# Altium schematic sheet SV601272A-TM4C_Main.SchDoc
size 431 x 279 mm; Date: Not shown in title block; ApprovedBy: Not shown in title block; CheckedBy: Not shown in title block; Author: Not shown in title block; CompanyName: Not shown in title block; Engineer: Not shown in title block; Organization: Not shown in title block; Address1: Not shown in title block; Address2: Not shown in title block; Address3: Not shown in title block; Address4: Not shown in title block; DocumentNumber: 10; Revision: Use project parameter SCH_Rev; SheetNumber: 10; SheetTotal: 11; PageSetup: Record=PageOptions¦CenterHorizontal=True¦CenterVertical=True¦PrintScale=1.00¦XCorrection=1.00¦YCorrection=1.00¦PrintKind=0¦BorderSize=5000000¦LeftOffset=0¦BottomOffset=0¦Orientation=2¦PaperLength=1000¦PaperWidth=1000¦Scale=100¦PaperSource=15¦PrintQuality=600¦MediaType=1¦DitherType=10¦PaperKind=Letter¦PrintScaleMode=1
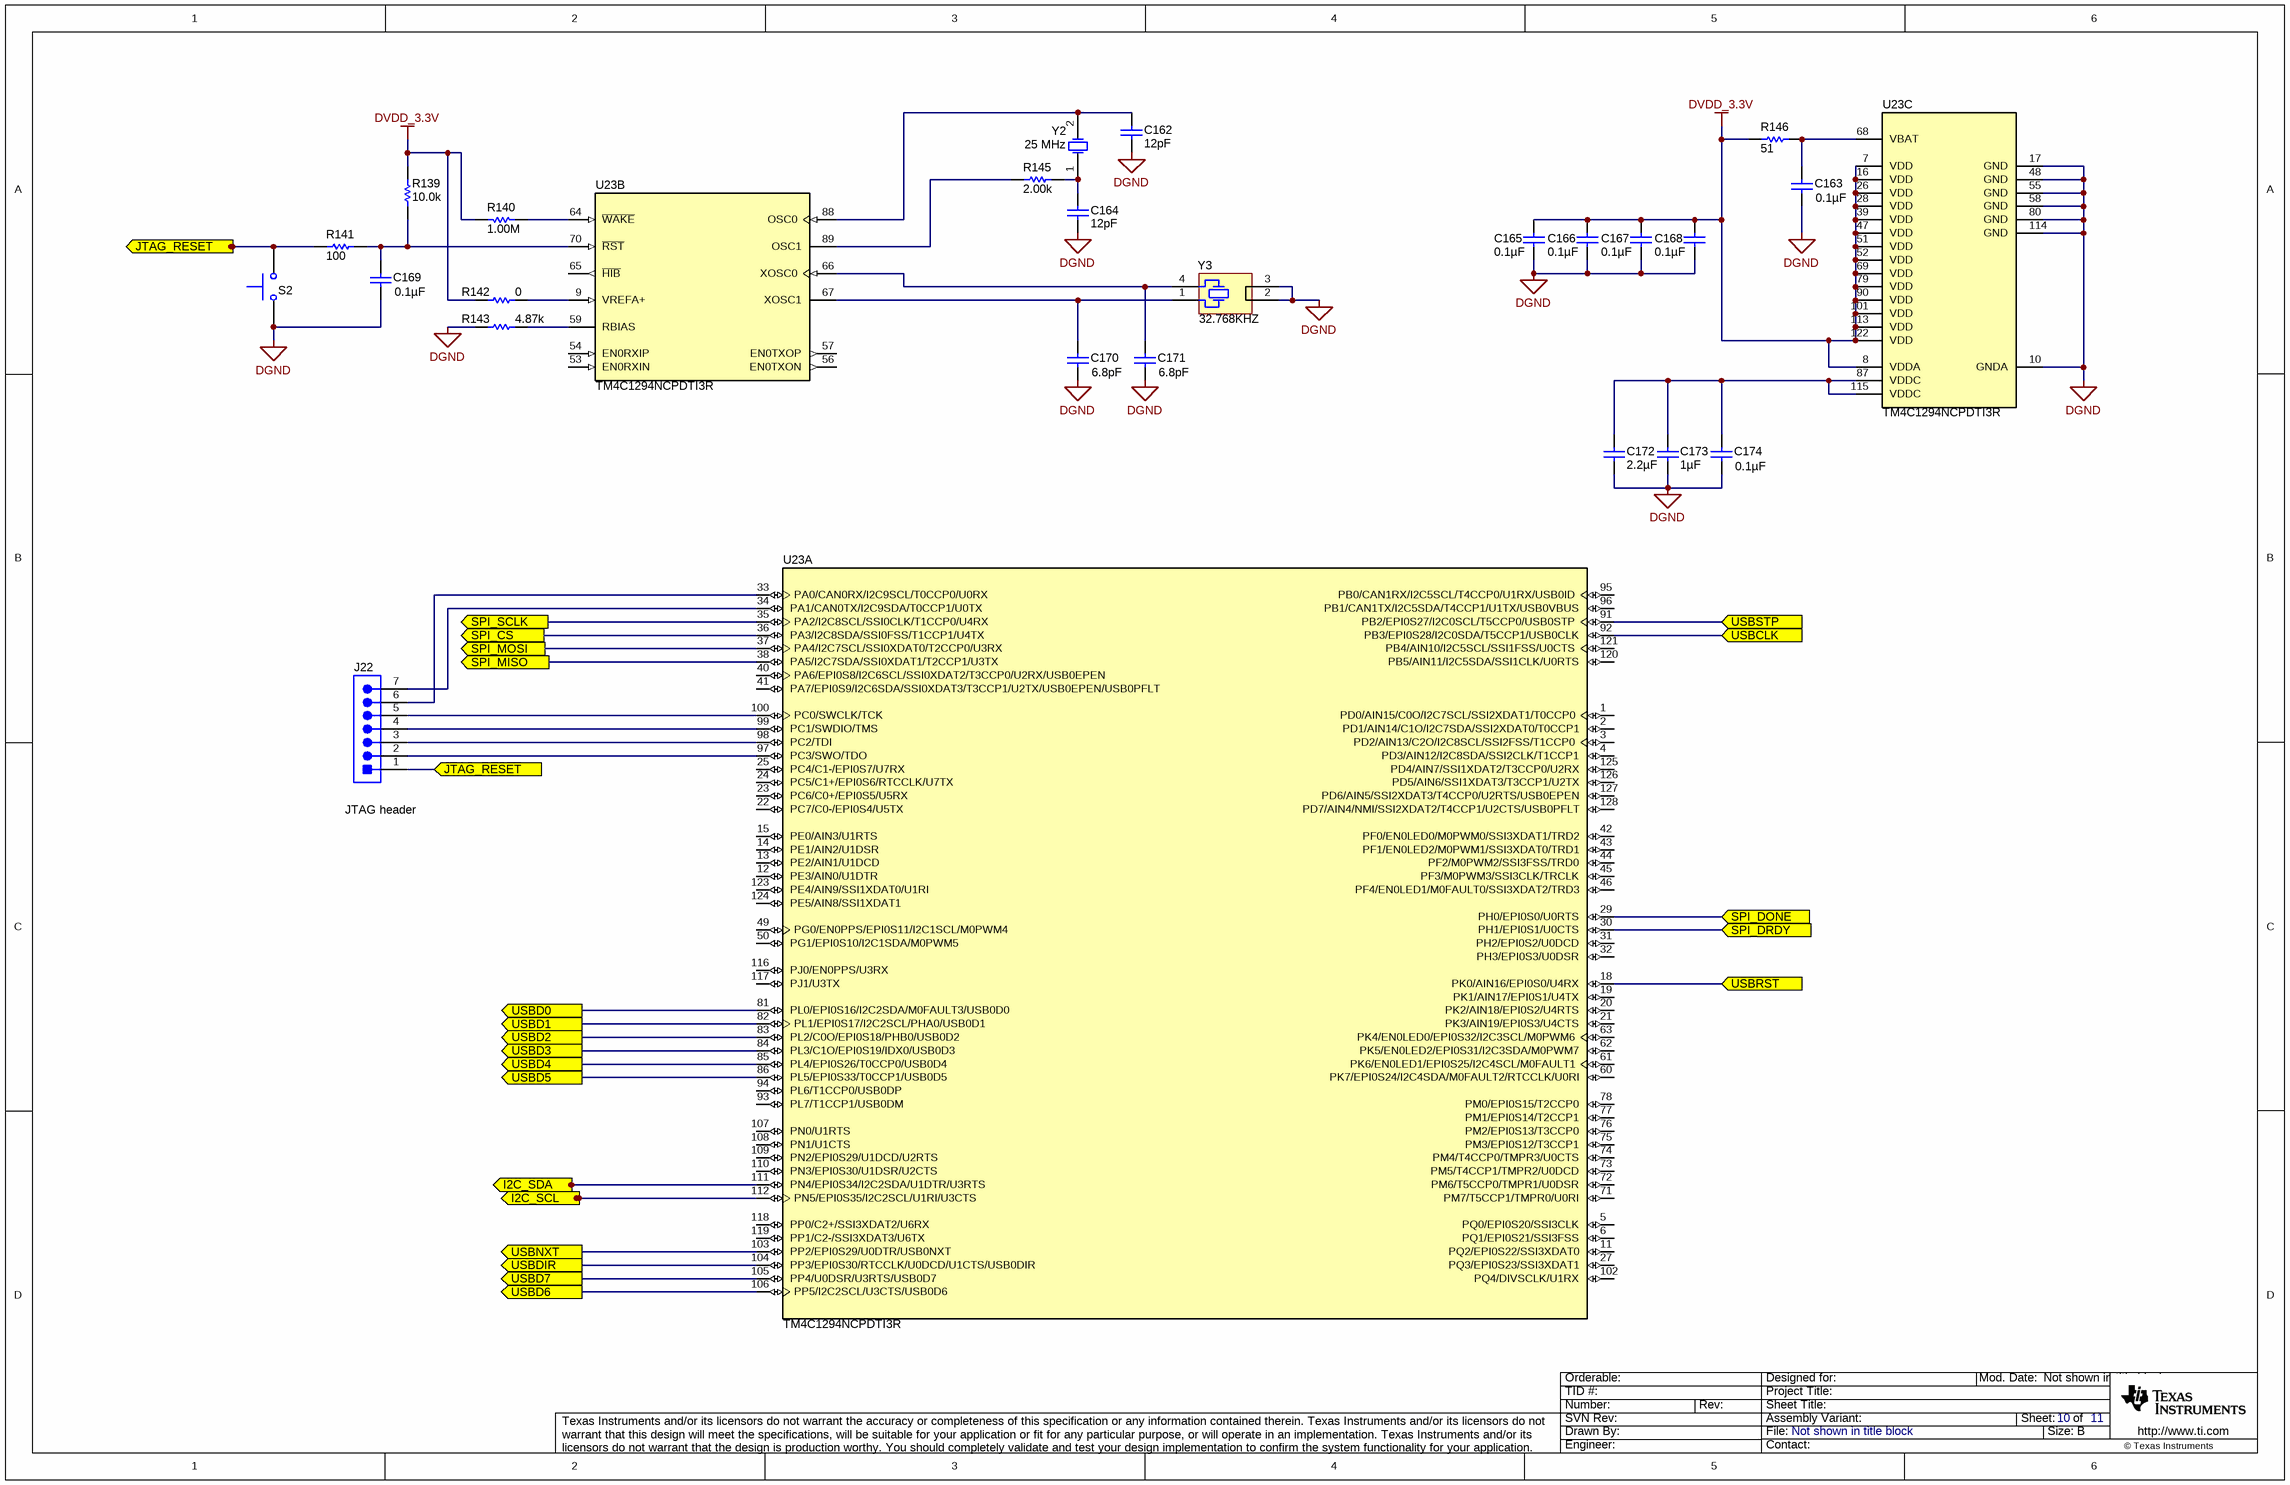
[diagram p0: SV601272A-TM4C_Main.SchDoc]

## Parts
C162  ValueDisplayed: 12pF  [0603]  (hidden comment: C0603C120J5GACTU)
C163  ValueDisplayed: 0.1µF  [0603]  (hidden comment: 06033C104JAT2A)
C164  ValueDisplayed: 12pF  [0603]  (hidden comment: C0603C120J5GACTU)
C165  ValueDisplayed: 0.1µF  [0603]  (hidden comment: 06033C104JAT2A)
C166  ValueDisplayed: 0.1µF  [0603]  (hidden comment: 06033C104JAT2A)
C167  ValueDisplayed: 0.1µF  [0603]  (hidden comment: 06033C104JAT2A)
C168  ValueDisplayed: 0.1µF  [0603]  (hidden comment: 06033C104JAT2A)
C169  ValueDisplayed: 0.1µF  [0603]  (hidden comment: 06033C104JAT2A)
C170  ValueDisplayed: 6.8pF  [0603]  (hidden comment: 06035A6R8CAT2A)
C171  ValueDisplayed: 6.8pF  [0603]  (hidden comment: 06035A6R8CAT2A)
C172  ValueDisplayed: 2.2µF  [0603]  (hidden comment: GRM188R6YA225KA12D)
C173  ValueDisplayed: 1µF  [0603]  (hidden comment: GRM188R71E105KA12D)
C174  ValueDisplayed: 0.1µF  [0603]  (hidden comment: 06033C104JAT2A)
J22  TSW-107-07-G-S  [TSW-107-07-G-S]  (value not drawn)
R139  ValueDisplayed: 10.0k  [0603]  (hidden comment: CRCW060310K0FKEA)
R140  ValueDisplayed: 1.00M  [0603]  (hidden comment: CRCW06031M00FKEA)
R141  ValueDisplayed: 100  [0603]  (hidden comment: CRCW0603100RFKEA)
R142  ValueDisplayed: 0  [0603]  (hidden comment: CRCW06030000Z0EA)
R143  ValueDisplayed: 4.87k  [0603]  (hidden comment: CRCW06034K87FKEA)
R145  ValueDisplayed: 2.00k  [0603]  (hidden comment: CRCW06032K00FKEA)
R146  ValueDisplayed: 51  [0603]  (hidden comment: CRCW060351R0JNEA)
S2  TL1015AF160QG  [SW_TL1015AF160QG]  (value not drawn)
U23  TM4C1294NCPDTI3R  [PDT0128A]  (parts A,B,C of 3)
Y2  Frequency: 25 MHz  [XTAL_ABM3]  (hidden comment: ABM3-25.000MHZ-D2Y-T)
Y3  Frequency: 32.768KHZ  [Seiko_SSP-T]  (hidden comment: SSPT7F-7PF20-R)

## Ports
I2C_SCL, I2C_SDA, JTAG_RESET, SPI_CS, SPI_DONE, SPI_DRDY, SPI_MISO, SPI_MOSI, SPI_SCLK, USBCLK, USBD0, USBD1, USBD2, USBD3, USBD4, USBD5, USBD6, USBD7, USBDIR, USBNXT, USBRST, USBSTP

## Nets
DGND: C162.2 C163.1 C164.2 C165.1 C166.1 C167.1 C168.1 C169.1 C170.1 C171.1 C172.2 C173.2 C174.1 R143.2 S2.1 U23.10(GNDA) U23.17(GND) U23.48(GND) U23.55(GND) U23.58(GND) U23.80(GND) U23.114(GND) Y3.2 Y3.3
DVDD_3.3V: C165.2 C166.2 C167.2 C168.2 R139.2 R140.2 R142.1 R146.1 U23.7(VDD) U23.8(VDDA) U23.16(VDD) U23.26(VDD) U23.28(VDD) U23.39(VDD) U23.47(VDD) U23.51(VDD) U23.52(VDD) U23.69(VDD) U23.79(VDD) U23.90(VDD) U23.101(VDD) U23.113(VDD) U23.122(VDD)
I2C_SCL: U23.112(PN5/EPI0S35/I2C2SCL/U1RI/U3CTS) ; port I2C_SCL
I2C_SDA: U23.111(PN4/EPI0S34/I2C2SDA/U1DTR/U3RTS) ; port I2C_SDA
JTAG_RESET: J22.1 R141.1 S2.2 ; port JTAG_RESET
SPI_CS: U23.36(PA3/I2C8SDA/SSI0FSS/T1CCP1/U4TX) ; port SPI_CS
SPI_DONE: U23.29(PH0/EPI0S0/U0RTS) ; port SPI_DONE
SPI_DRDY: U23.30(PH1/EPI0S1/U0CTS) ; port SPI_DRDY
SPI_MISO: U23.38(PA5/I2C7SDA/SSI0XDAT1/T2CCP1/U3TX) ; port SPI_MISO
SPI_MOSI: U23.37(PA4/I2C7SCL/SSI0XDAT0/T2CCP0/U3RX) ; port SPI_MOSI
SPI_SCLK: U23.35(PA2/I2C8SCL/SSI0CLK/T1CCP0/U4RX) ; port SPI_SCLK
USBCLK: U23.92(PB3/EPI0S28/I2C0SDA/T5CCP1/USB0CLK) ; port USBCLK
USBD0: U23.81(PL0/EPI0S16/I2C2SDA/M0FAULT3/USB0D0) ; port USBD0
USBD1: U23.82(PL1/EPI0S17/I2C2SCL/PHA0/USB0D1) ; port USBD1
USBD2: U23.83(PL2/C0O/EPI0S18/PHB0/USB0D2) ; port USBD2
USBD3: U23.84(PL3/C1O/EPI0S19/IDX0/USB0D3) ; port USBD3
USBD4: U23.85(PL4/EPI0S26/T0CCP0/USB0D4) ; port USBD4
USBD5: U23.86(PL5/EPI0S33/T0CCP1/USB0D5) ; port USBD5
USBD6: U23.106(PP5/I2C2SCL/U3CTS/USB0D6) ; port USBD6
USBD7: U23.105(PP4/U0DSR/U3RTS/USB0D7) ; port USBD7
USBDIR: U23.104(PP3/EPI0S30/RTCCLK/U0DCD/U1CTS/USB0DIR) ; port USBDIR
USBNXT: U23.103(PP2/EPI0S29/U0DTR/USB0NXT) ; port USBNXT
USBRST: U23.18(PK0/AIN16/EPI0S0/U4RX) ; port USBRST
USBSTP: U23.91(PB2/EPI0S27/I2C0SCL/T5CCP0/USB0STP) ; port USBSTP
NetC162_1: C162.1 U23.88(OSC0) Y2.2(OSC2)
NetC163_2: C163.2 R146.2 U23.68(VBAT)
NetC164_1: C164.1 R145.1 Y2.1(OSC1)
NetC169_2: C169.2 R139.1 R141.2 U23.70(~{RST})
NetC170_2: C170.2 U23.67(XOSC1) Y3.1
NetC171_2: C171.2 U23.66(XOSC0) Y3.4
NetC172_1: C172.1 C173.1 C174.2 U23.87(VDDC) U23.115(VDDC)
NetJ22_2: J22.2 U23.97(PC3/SWO/TDO)
NetJ22_3: J22.3 U23.98(PC2/TDI)
NetJ22_4: J22.4 U23.99(PC1/SWDIO/TMS)
NetJ22_5: J22.5 U23.100(PC0/SWCLK/TCK)
NetJ22_6: J22.6 U23.33(PA0/CAN0RX/I2C9SCL/T0CCP0/U0RX)
NetJ22_7: J22.7 U23.34(PA1/CAN0TX/I2C9SDA/T0CCP1/U0TX)
NetR140_1: R140.1 U23.64(~{WAKE})
NetR142_2: R142.2 U23.9(VREFA+)
NetR143_1: R143.1 U23.59(RBIAS)
NetR145_2: R145.2 U23.89(OSC1)

Not connected (* = marked no-connect by the designer): U23 1(PD0/AIN15/C0O/I2C7SCL/SSI2XDAT1/T0CCP0) 2(PD1/AIN14/C1O/I2C7SDA/SSI2XDAT0/T0CCP1) 3(PD2/AIN13/C2O/I2C8SCL/SSI2FSS/T1CCP0) 4(PD3/AIN12/I2C8SDA/SSI2CLK/T1CCP1) 5(PQ0/EPI0S20/SSI3CLK) 6(PQ1/EPI0S21/SSI3FSS) 11(PQ2/EPI0S22/SSI3XDAT0) 12(PE3/AIN0/U1DTR) 13(PE2/AIN1/U1DCD) 14(PE1/AIN2/U1DSR) 15(PE0/AIN3/U1RTS) 19(PK1/AIN17/EPI0S1/U4TX) 20(PK2/AIN18/EPI0S2/U4RTS) 21(PK3/AIN19/EPI0S3/U4CTS) 22(PC7/C0-/EPI0S4/U5TX) 23(PC6/C0+/EPI0S5/U5RX) 24(PC5/C1+/EPI0S6/RTCCLK/U7TX) 25(PC4/C1-/EPI0S7/U7RX) 27(PQ3/EPI0S23/SSI3XDAT1) 31(PH2/EPI0S2/U0DCD) 32(PH3/EPI0S3/U0DSR) 40(PA6/EPI0S8/I2C6SCL/SSI0XDAT2/T3CCP0/U2RX/USB0EPEN) 41(PA7/EPI0S9/I2C6SDA/SSI0XDAT3/T3CCP1/U2TX/USB0EPEN/USB0PFLT) 42(PF0/EN0LED0/M0PWM0/SSI3XDAT1/TRD2) 43(PF1/EN0LED2/M0PWM1/SSI3XDAT0/TRD1) 44(PF2/M0PWM2/SSI3FSS/TRD0) 45(PF3/M0PWM3/SSI3CLK/TRCLK) 46(PF4/EN0LED1/M0FAULT0/SSI3XDAT2/TRD3) 49(PG0/EN0PPS/EPI0S11/I2C1SCL/M0PWM4) 50(PG1/EPI0S10/I2C1SDA/M0PWM5) 53(EN0RXIN) 54(EN0RXIP) 56(EN0TXON) 57(EN0TXOP) 60(PK7/EPI0S24/I2C4SDA/M0FAULT2/RTCCLK/U0RI) 61(PK6/EN0LED1/EPI0S25/I2C4SCL/M0FAULT1) 62(PK5/EN0LED2/EPI0S31/I2C3SDA/M0PWM7) 63(PK4/EN0LED0/EPI0S32/I2C3SCL/M0PWM6) 65(~{HIB}) 71(PM7/T5CCP1/TMPR0/U0RI) 72(PM6/T5CCP0/TMPR1/U0DSR) 73(PM5/T4CCP1/TMPR2/U0DCD) 74(PM4/T4CCP0/TMPR3/U0CTS) 75(PM3/EPI0S12/T3CCP1) 76(PM2/EPI0S13/T3CCP0) 77(PM1/EPI0S14/T2CCP1) 78(PM0/EPI0S15/T2CCP0) 93(PL7/T1CCP1/USB0DM) 94(PL6/T1CCP0/USB0DP) 95(PB0/CAN1RX/I2C5SCL/T4CCP0/U1RX/USB0ID) 96(PB1/CAN1TX/I2C5SDA/T4CCP1/U1TX/USB0VBUS) 102(PQ4/DIVSCLK/U1RX) 107(PN0/U1RTS) 108(PN1/U1CTS) 109(PN2/EPI0S29/U1DCD/U2RTS) 110(PN3/EPI0S30/U1DSR/U2CTS) 116(PJ0/EN0PPS/U3RX) 117(PJ1/U3TX) 118(PP0/C2+/SSI3XDAT2/U6RX) 119(PP1/C2-/SSI3XDAT3/U6TX) 120(PB5/AIN11/I2C5SDA/SSI1CLK/U0RTS) 121(PB4/AIN10/I2C5SCL/SSI1FSS/U0CTS) 123(PE4/AIN9/SSI1XDAT0/U1RI) 124(PE5/AIN8/SSI1XDAT1) 125(PD4/AIN7/SSI1XDAT2/T3CCP0/U2RX) 126(PD5/AIN6/SSI1XDAT3/T3CCP1/U2TX) 127(PD6/AIN5/SSI2XDAT3/T4CCP0/U2RTS/USB0EPEN) 128(PD7/AIN4/NMI/SSI2XDAT2/T4CCP1/U2CTS/USB0PFLT)

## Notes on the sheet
- (near J22) JTAG header

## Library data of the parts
C162 C164 = C0603C120J5GACTU: CAP, CERM, 12 pF, 50 V, +/- 5%, C0G/NP0, 0603; Manufacturer: Kemet; Polarized: N; CompType: Capacitor; Value: 12pF; U/M: EA; Cap_F: 0.000000000012; Tolerance_%: 5; Value1: Unknown; VDC_V: 50; Value2: 50V; TaMin_C: -55; TaMax_C: 125; AEC Category: Q200
C163 C165-C169 C174 = 06033C104JAT2A: CAP, CERM, 0.1 µF, 25 V, +/- 5%, X7R, 0603; Manufacturer: AVX; Polarized: N; CompType: Capacitor; Value: 0.1uF; U/M: EA; Cap_F: 0.0000001; Tolerance_%: 5; ESR_ohm: 0.05; Value1: 0.05 ohm; VDC_V: 25; Value2: 25V; TaMin_C: -55; TaMax_C: 125; AEC Category: Q200
C170 C171 = 06035A6R8CAT2A: CAP, CERM, 6.8 pF, 50 V, +/- 4%, C0G/NP0, 0603; Manufacturer: AVX; Polarized: N; CompType: Capacitor; Value: 6.8pF; U/M: EA; Cap_F: 0.0000000000068; Tolerance_%: 4; ESR_ohm: 0.505; Value1: 0.505 ohm; VDC_V: 50; Value2: 50V; TaMin_C: -55; TaMax_C: 125; AEC Category: Q200
C172 = GRM188R6YA225KA12D: CAP, CERM, 2.2 µF, 35 V, +/- 10%, X5R, 0603; Manufacturer: MuRata; Polarized: N; CompType: Capacitor; Value: 2.2uF; U/M: EA; Cap_F: 0.0000022; Tolerance_%: 10; Value1: Unknown; VDC_V: 35; Value2: 35V; TaMin_C: -55; TaMax_C: 85; AEC Category: Q200
C173 = GRM188R71E105KA12D: CAP, CERM, 1 µF, 25 V, +/- 10%, X7R, 0603; Manufacturer: MuRata; Polarized: N; CompType: Capacitor; Value: 1uF; U/M: EA; Cap_F: 0.000001; Tolerance_%: 10; Value1: Unknown; VDC_V: 25; Value2: 25V; TaMin_C: -55; TaMax_C: 125; AEC Category: Q200
J22 = TSW-107-07-G-S: Header, 100mil, 7x1, Gold, TH; Manufacturer: Samtec; SymbolCreator: a0411947; U/M: EA
R139 = CRCW060310K0FKEA: RES, 10.0 k, 1%, 0.1 W, 0603; Manufacturer: Vishay-Dale; CompType: Resistor; Value: 10.0k; Res_ohm: 10000; Value_Code: 10k0; Tolerance_%: 1; Power_W: 0.1; Value2: 0.1W; VDC_V: 75; TempCo: 100 ppm/C; EIA_Code: E96; U/M: EA; AEC Category: Q200
R140 = CRCW06031M00FKEA: RES, 1.00 M, 1%, 0.1 W, 0603; Manufacturer: Vishay-Dale; CompType: Resistor; Value: 1.00Meg; Res_ohm: 1000000; Value_Code: 1M00; Tolerance_%: 1; Power_W: 0.1; Value2: 0.1W; VDC_V: 75; TempCo: 100 ppm/C; EIA_Code: E96; U/M: EA; AEC Category: Q200
R141 = CRCW0603100RFKEA: RES, 100, 1%, 0.1 W, 0603; Manufacturer: Vishay-Dale; CompType: Resistor; Value: 100; Value_Code: 100R; Tolerance_%: 1; Power_W: 0.1; Value2: 0.1W; VDC_V: 75; TempCo: 100 ppm/C; EIA_Code: E96; U/M: EA; AEC Category: Q200
R142 = CRCW06030000Z0EA: RES, 0, 5%, 0.1 W, 0603; Manufacturer: Vishay-Dale; CompType: Resistor; Value: 0; Value_Code: 0000; Tolerance_%: 5; Power_W: 0.1; Value2: 0.1W; VDC_V: 75; TempCo: 200 ppm/C; EIA_Code: E24; U/M: EA; AEC Category: Q200
R143 = CRCW06034K87FKEA: RES, 4.87 k, 1%, 0.1 W, 0603; Manufacturer: Vishay-Dale; CompType: Resistor; Value: 4.87k; Res_ohm: 4870; Value_Code: 4k87; Tolerance_%: 1; Power_W: 0.1; Value2: 0.1W; VDC_V: 75; TempCo: 100 ppm/C; EIA_Code: E96; U/M: EA; AEC Category: Q200
R145 = CRCW06032K00FKEA: RES, 2.00 k, 1%, 0.1 W, 0603; Manufacturer: Vishay-Dale; CompType: Resistor; Value: 2.00k; Res_ohm: 2000; Value_Code: 2k00; Tolerance_%: 1; Power_W: 0.1; Value2: 0.1W; VDC_V: 75; TempCo: 100 ppm/C; EIA_Code: E96; U/M: EA; AEC Category: Q200
R146 = CRCW060351R0JNEA: RES, 51, 5%, 0.1 W, 0603; Manufacturer: Vishay-Dale; CompType: Resistor; Value: 51; Value_Code: 51R0; Tolerance_%: 5; Power_W: 0.1; Value2: 0.1W; VDC_V: 75; TempCo: 200 ppm/C; EIA_Code: E24; U/M: EA; AEC Category: Q200
S2 = TL1015AF160QG: Switch, Tactile, SPST-NO, 0.05A, 12V, SMT; Manufacturer: E-Switch; SymbolCreator: a0412235; VDC_V: 12; SwitchFunction: Off-Mom; PositionCount: 1; CurrentRating_mA: 50
U23 = CMP-0029864-2: Tiva C Series Microcontroller, 1024 KB Flash, 256 KB SRAM, 12 Bit, 20 Channels, -40 to 85 degC, 128-Pin TQFP (PDT), Green (RoHS & no Sb/Br), Tape and Reel; Manufacturer: Texas Instruments; ADC Channels: 20; CPU: ARM Cortex-M4; Flash: 1024 KB; ADC Resolution: 12 Bits; Max Speed: 120 MHz; SRAM: 256 KB; SizeAreaWB_mm2: 324.0; SizeArea_mm2: 256.0; SizeX_mm: 16.0; SizeZ_mm: 1.2; CompType: IC
Y2 = ABM3-25.000MHZ-D2Y-T: Crystal, 25 MHz, 18 pF, SMD; Manufacturer: Abracon Corportation; SymbolCreator: a0412235; U/M: EA; TaMin_C: -40; TaMax_C: 85; Frequency Stability: ±30ppm
Y3 = SSPT7F-7PF20-R: CRYSTAL, 32.768KHZ, 7PF, SMD; Manufacturer: Seiko Instruments; SymbolCreator: x0208325; U/M: EA; TaMin_C: -40; TaMax_C: 85; Frequency Stability: ±20ppm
